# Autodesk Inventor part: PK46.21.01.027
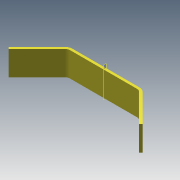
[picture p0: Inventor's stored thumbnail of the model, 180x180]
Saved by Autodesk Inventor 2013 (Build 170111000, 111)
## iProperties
Created: 2005-04
Part Number: PK46.21.01.027
Material: Steel, Mild
Document SubType Name: Sheet Metal
Designer: salex
Manufacturer: Standard
Standards Organization: Custom
Density: 7.86 g/cm^3
Sheet Metal Rule: Default
Author: salex
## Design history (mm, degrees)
node "ФлнОтгиб1"
node "РабПлоскость1"
body "Solid1"
sketch "Эскиз1"
  geometry: L1 (0, 0)-(120, 120); L2 (120, 120)-(410, 120); L3 (410, 120)-(530, 0)
  constraints: 6 end point, 1 horizontal, 1 perpendicular, 1 other
  dimensions: "d0" = 530 distance of L3.end L1.start; "d1" = 120 distance from line of L1.start L2; "d2" = 0 vertical distance of L3.end L1.start; "d3" = 290 distance of L1.end L2.end
feature "Плакирование1" dims "d4" = 100, "d5" = 10 (= BendReliefWidth), "d7" = 20 (= MinimumRemnant), "d9" = 20 (= BendRadius), "d10" = 10, "Thickness" = 10
feature "Изгиб1" dims "d5" = 10 (= BendReliefWidth), "d6" = 5 (= BendReliefDepth), "d7" = 20 (= MinimumRemnant), "d8" = 20 (= BendRadius), "d9" = 20 (= BendRadius), "d10" = 10, "SeamGap" = 0.01, "Thickness" = 10
other parameters: "BendRadius" = 20, "BendReliefDepth" = 5 (= 0.5 x Thickness)
